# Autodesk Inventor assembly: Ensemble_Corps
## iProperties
Shininess: 64.0
Length Units: 11269
Angle Units: 11279
Time Units: 11290
Mass Units: 11283
Length Display Precision: 3
Angle Display Precision: 2
Compacted: True
Created: 2004-05
Part Number: Ensemble_Corps
Document SubType Name: Assembly
Designer: David
Density: 0.0
Volumn: 0.0
Area: 0.0
PropertySet Name: Model Information
Control State: 0
Master: False
Checked Out: False
Author: David
